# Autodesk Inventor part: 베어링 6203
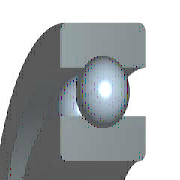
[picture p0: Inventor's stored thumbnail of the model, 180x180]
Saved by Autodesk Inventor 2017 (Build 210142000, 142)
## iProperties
IsCustomPart: 1
Created: 2012-02
Part Number: 베어링 6203
Material: 강철, 연강
Description: 깊은 그루브 볼 베어링
Document SubType Name: Modeling
Standard: KS B 2023
Designer: mduedu
Standards Organization: KS
Language: ko-KR
Size Designation: 6203 - 17 x 40 x 12
Categories: <MemberInstance><Categories><Category DisplayName="샤프트 부품" InternalName="7f7aeb1f-a693-4053-b835-cee3144e0d98" Mnemonic="SHFT"><Category DisplayName="베어링" Inter
Density: 7.85 g/cm^3
Appearance: 노란색
Mass: 64.8982 g
Surface Area: 64.3582 cm^2
Volume: 8.26729 cm^3
Author: mduedu
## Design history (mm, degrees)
sketch "스케치" dims "d0" = 5.98 (= -0.26 x WD + 0.26 x BD)
  geometry: L1 (3.01, 14.25)-(8.99, 14.25); L2 (6, 14.25)-(6, 11.26); L3 (6, 14.25)-(6, 17.24); L4 (3.778, 12.249)-(0, 12.249); L5 (0, 8.5)-(12, 8.5); L6 (3.778, 16.251)-(0, 16.251); L7 (0, 20)-(12, 20); L8 (12, 8.5)-(12, 12.249); L9 (8.222, 12.249)-(12, 12.249); L10 (8.222, 16.251)-(12, 16.251); L11 (12, 20)-(12, 16.251); L12 (-1.4, 0)-(8.4, 0) reference; L13 (0, -0.3)-(0, 5.3) reference
  constraints: 22 end point, 4 point on line, 2 collinear, 2 perpendicular, 2 symmetric about line, 1 midpoint, 1 parallel, 14 other
  dimensions: "d9" = 17 diameter of L5 L12 (= WD); "d11" = 40 diameter of L7 L12 (= BD); "d12" = 12 distance between parallel lines of L8 L13 (= KB); "d13" = 24.498 diameter of L9 L12 (= 0.326 x BD + 0.674 x WD)
revolve "본체" stored, may be unused: angle "d6" = 90 deg
revolve "볼" stored, may be unused: angle "d7" = 90 deg
pattern_circular "IDS_ARRAYBALL[SIMPL:T]" dims angle "d3" = 360 deg
body "Solid1"
fillet "모깎기1" dims "d1" = 0.6 (= KRS)
other parameters: "WD" = 17 [user parameter; used in 5 equation terms], "BD" = 40 [user parameter; used in 5 equation terms], "KB" = 12 [user parameter; used in 1 equation term], "KRS" = 0.6 [user parameter; used in 1 equation term], "d4" = 0, "d5" = 0, "d8" = 0, "d14" = 0, "d15" = 0, "BBA" = 0 [user parameter], "BC0" = 4750000 [user parameter], "BC" = 9560000 [user parameter], "WR" = 8.5 (= 0.5 x WD) [user parameter]
